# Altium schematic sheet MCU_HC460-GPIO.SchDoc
size A4; CompanyName: 广州立功科技股份有限公司; DocumentNumber: 6; SheetNumber: 6; SheetTotal: 15; PageSetup: Record=PageOptions|CenterHorizontal=True|CenterVertical=True|PrintScale=1.00|XCorrection=1.00|YCorrection=1.00|PrintKind=0|BorderSize=5000000|LeftOffset=0|BottomOffset=0|Orientation=2|PaperLength=1000|PaperWidth=1000|Scale=100|PaperSource=7|PrintQuality=600|MediaType=1|DitherType=10|PaperKind=A4|PrintScaleMode=1; DesignDate: 2021.1; SheetName: MCU_HC460_GPIO; SheetVersion: Rev.A; SheetDescription: 单片机引脚图
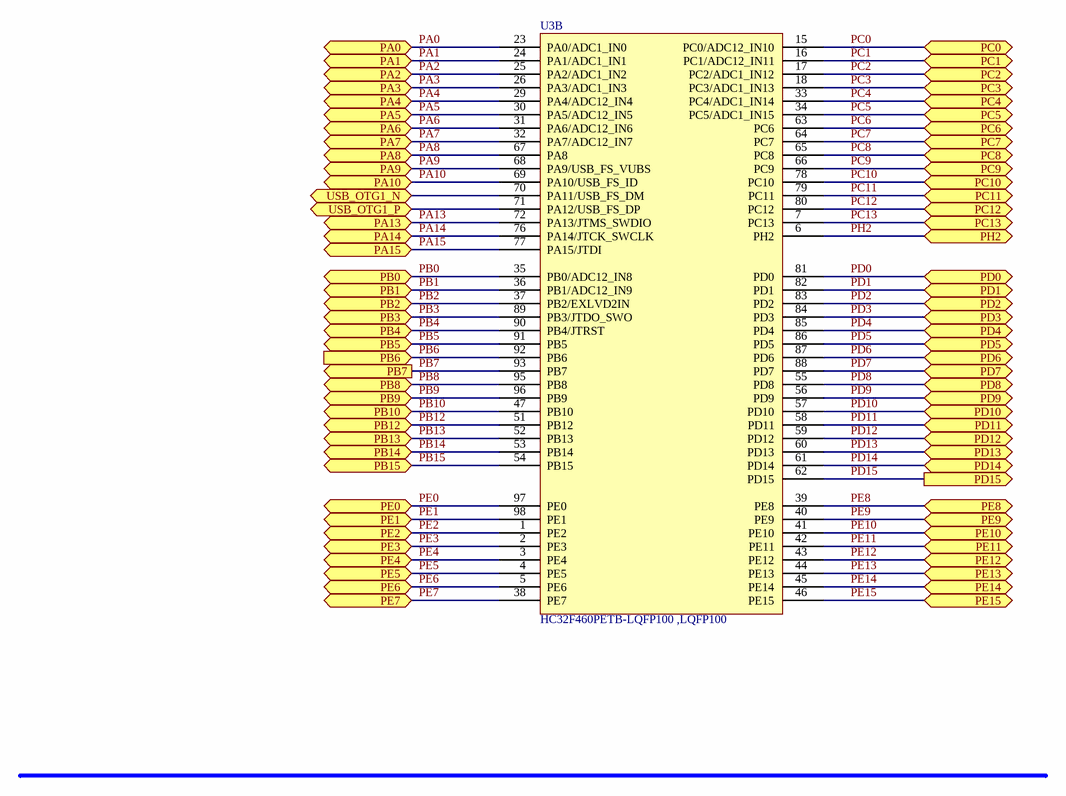
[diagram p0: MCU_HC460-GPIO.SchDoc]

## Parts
U3  HC32F460PETB-LQFP100 / ,LQFP100  [QFP50P1600X1600X160-100N]  (part B of 2)

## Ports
PA0, PA1, PA2, PA3, PA4, PA5, PA6, PA7, PA8, PA9, PA10, PA13, PA14, PA15, PB0, PB1, PB2, PB3, PB4, PB5, PB6 (in), PB7 (out), PB8, PB9, PB10, PB12, PB13, PB14, PB15, PC0, PC1, PC2, PC3, PC4, PC5, PC6, PC7, PC8, PC9, PC10, PC11, PC12, PC13, PD0, PD1, PD2, PD3, PD4, PD5, PD6, PD7, PD8, PD9, PD10, PD11, PD12, PD13, PD14, PD15 (out), PE0, PE1, PE2, PE3, PE4, PE5, PE6, PE7, PE8, PE9, PE10, PE11, PE12, PE13, PE14, PE15, PH2, USB_OTG1_N, USB_OTG1_P

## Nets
PA0: U3.23(PA0/ADC1_IN0) ; port PA0
PA1: U3.24(PA1/ADC1_IN1) ; port PA1
PA2: U3.25(PA2/ADC1_IN2) ; port PA2
PA3: U3.26(PA3/ADC1_IN3) ; port PA3
PA4: U3.29(PA4/ADC12_IN4) ; port PA4
PA5: U3.30(PA5/ADC12_IN5) ; port PA5
PA6: U3.31(PA6/ADC12_IN6) ; port PA6
PA7: U3.32(PA7/ADC12_IN7) ; port PA7
PA8: U3.67(PA8) ; port PA8
PA9: U3.68(PA9/USB_FS_VUBS) ; port PA9
PA10: U3.69(PA10/USB_FS_ID) ; port PA10
PA13: U3.72(PA13/JTMS_SWDIO) ; port PA13
PA14: U3.76(PA14/JTCK_SWCLK) ; port PA14
PA15: U3.77(PA15/JTDI) ; port PA15
PB0: U3.35(PB0/ADC12_IN8) ; port PB0
PB1: U3.36(PB1/ADC12_IN9) ; port PB1
PB2: U3.37(PB2/EXLVD2IN) ; port PB2
PB3: U3.89(PB3/JTDO_SWO) ; port PB3
PB4: U3.90(PB4/JTRST) ; port PB4
PB5: U3.91(PB5) ; port PB5
PB6: U3.92(PB6) ; port PB6
PB7: U3.93(PB7) ; port PB7
PB8: U3.95(PB8) ; port PB8
PB9: U3.96(PB9) ; port PB9
PB10: U3.47(PB10) ; port PB10
PB12: U3.51(PB12) ; port PB12
PB13: U3.52(PB13) ; port PB13
PB14: U3.53(PB14) ; port PB14
PB15: U3.54(PB15) ; port PB15
PC0: U3.15(PC0/ADC12_IN10) ; port PC0
PC1: U3.16(PC1/ADC12_IN11) ; port PC1
PC2: U3.17(PC2/ADC1_IN12) ; port PC2
PC3: U3.18(PC3/ADC1_IN13) ; port PC3
PC4: U3.33(PC4/ADC1_IN14) ; port PC4
PC5: U3.34(PC5/ADC1_IN15) ; port PC5
PC6: U3.63(PC6) ; port PC6
PC7: U3.64(PC7) ; port PC7
PC8: U3.65(PC8) ; port PC8
PC9: U3.66(PC9) ; port PC9
PC10: U3.78(PC10) ; port PC10
PC11: U3.79(PC11) ; port PC11
PC12: U3.80(PC12) ; port PC12
PC13: U3.7(PC13) ; port PC13
PD0: U3.81(PD0) ; port PD0
PD1: U3.82(PD1) ; port PD1
PD2: U3.83(PD2) ; port PD2
PD3: U3.84(PD3) ; port PD3
PD4: U3.85(PD4) ; port PD4
PD5: U3.86(PD5) ; port PD5
PD6: U3.87(PD6) ; port PD6
PD7: U3.88(PD7) ; port PD7
PD8: U3.55(PD8) ; port PD8
PD9: U3.56(PD9) ; port PD9
PD10: U3.57(PD10) ; port PD10
PD11: U3.58(PD11) ; port PD11
PD12: U3.59(PD12) ; port PD12
PD13: U3.60(PD13) ; port PD13
PD14: U3.61(PD14) ; port PD14
PD15: U3.62(PD15) ; port PD15
PE0: U3.97(PE0) ; port PE0
PE1: U3.98(PE1) ; port PE1
PE2: U3.1(PE2) ; port PE2
PE3: U3.2(PE3) ; port PE3
PE4: U3.3(PE4) ; port PE4
PE5: U3.4(PE5) ; port PE5
PE6: U3.5(PE6) ; port PE6
PE7: U3.38(PE7) ; port PE7
PE8: U3.39(PE8) ; port PE8
PE9: U3.40(PE9) ; port PE9
PE10: U3.41(PE10) ; port PE10
PE11: U3.42(PE11) ; port PE11
PE12: U3.43(PE12) ; port PE12
PE13: U3.44(PE13) ; port PE13
PE14: U3.45(PE14) ; port PE14
PE15: U3.46(PE15) ; port PE15
PH2: U3.6(PH2) ; port PH2
USB_OTG1_N: U3.70(PA11/USB_FS_DM) ; port USB_OTG1_N
USB_OTG1_P: U3.71(PA12/USB_FS_DP) ; port USB_OTG1_P

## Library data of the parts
U3 = 08.20.00166: HC32F460PETB-LQFP100 / ,LQFP100,华大HDSC; 名称: 集成电路; 封装: LQFP-100; 厂商: HDSC; 贴片和直插: SMT; PCB备注: 210219ZW; 器件优选方案: 待导入物料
